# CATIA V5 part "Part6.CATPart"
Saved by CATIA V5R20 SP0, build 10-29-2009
Part number: 1DIN7984516_DIN 7984 - M5 x 16 --- 16C
Revision: ANY
Definition: UNKNOWN
Nomenclature: 1DIN7984516_DIN 7984 - M5 x 16 --- 16C
Source: Unknown
Bounding box of the stored display mesh (mm): x 0 to 19.5, y -4.25 to 4.25, z -4.25 to 4.25
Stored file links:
  C:\Users\Utente\Desktop\IO LAVORO\3D X SITO CF\CUMSA\3D files PW\pw081030\pw081030_injection\Part6.CATPart
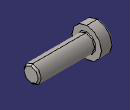
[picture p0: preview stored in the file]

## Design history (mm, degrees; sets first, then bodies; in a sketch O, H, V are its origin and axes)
Body1 "Hex" (main body)
  Solid1: solid without history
